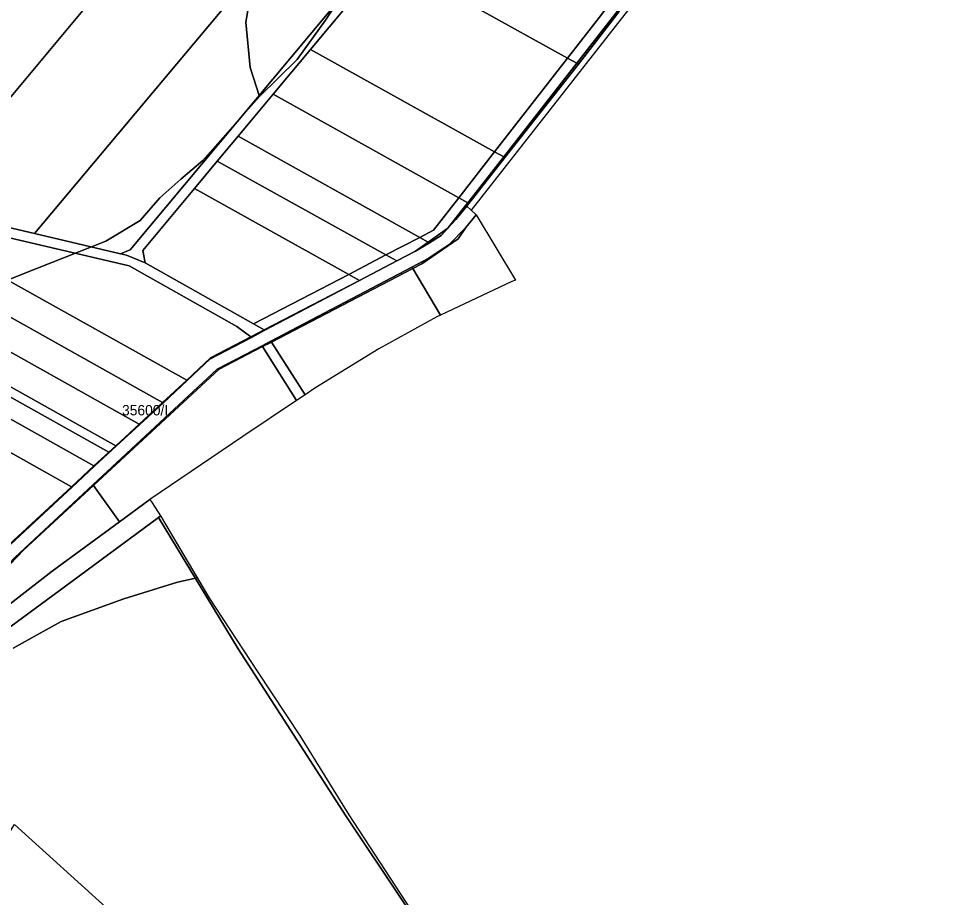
# Model space of a CAD drawing. Extents: x -541351 to -537540, y -1162694 to -1159725.
# Drawn here: x -537985.1 to -537540.1, y -1161335.6 to -1160910.2 of the extents above; entities that cross this region are included whole.
import ezdxf

# ---------------------------------------------------------------- set-up
doc = ezdxf.new("R2010")
doc.units = 0
for name, color, linetype in [('95560013', 7, 'Continuous'), ('95590013', 7, 'Continuous'), ('95610013', 7, 'Continuous'), ('95630013', 7, 'Continuous'), ('95640013', 7, 'Continuous'), ('95660013', 7, 'Continuous')]:
    doc.layers.add(name, color=color, linetype=linetype)

msp = doc.modelspace()

# ---------------------------------------------------------------- linework, layer by layer
at = {"layer": '95560013'}
for points in [[(-538045.37, -1160998.29), (-538077.91, -1160990.66), (-537915.59, -1160797.32), (-537871.51, -1160807.67), (-537952.32, -1160904.42), (-538033.13, -1161001.17)], [(-538033.13, -1161001.17), (-537952.32, -1160904.42), (-537871.51, -1160807.67), (-537815.26, -1160820.89), (-537977.34, -1161014.29)], [(-537815.26, -1160820.89), (-537776.51, -1160829.99), (-537775.04, -1160835.28), (-537853.06, -1160928.71), (-537931.08, -1161022.13), (-537935.72, -1161024.07), (-537977.34, -1161014.29)], [(-537806.91, -1160880.9), (-537790.61, -1160861.47), (-537786.25, -1160856.27), (-537699.93, -1160904.11), (-537704.14, -1160909.52), (-537719.59, -1160929.38)], [(-537806.91, -1160880.9), (-537719.59, -1160929.38), (-537754.86, -1160974.71), (-537843.94, -1160925.28)], [(-537861.98, -1160946.89), (-537843.94, -1160925.28), (-537754.86, -1160974.71), (-537772.19, -1160996.99)], [(-537878.89, -1160967.16), (-537861.98, -1160946.89), (-537772.19, -1160996.99), (-537784.39, -1161012.67), (-537791.07, -1161016.15)], [(-537791.07, -1161016.15), (-537807.37, -1161024.64), (-537888.95, -1160979.22), (-537878.89, -1160967.16)], [(-537825.4, -1161034.03), (-537899.97, -1160992.42), (-537888.95, -1160979.22), (-537807.37, -1161024.64)], [(-537825.4, -1161034.03), (-537871.46, -1161058.02), (-537923.87, -1161028.46), (-537925.02, -1161022.44), (-537899.97, -1160992.42)], [(-537903.69, -1161085.29), (-538044.43, -1161006.74), (-538039.9, -1161004.61), (-537931.57, -1161029.91), (-537879.46, -1161059.19), (-537872.72, -1161064.31), (-537892.24, -1161074.47)], [(-537903.69, -1161085.29), (-537915.45, -1161096.02), (-538051.5, -1161019.74), (-538044.43, -1161006.74)], [(-537941.41, -1161120.13), (-537948.57, -1161126.77), (-538071.97, -1161057.57), (-538067.56, -1161049.39)], [(-538071.97, -1161057.57), (-537948.57, -1161126.77), (-537959.49, -1161136.9), (-538078.6, -1161069.87)], [(-538017.76, -1161193.9), (-538116.49, -1161139.32), (-538078.6, -1161069.87), (-537959.49, -1161136.9), (-537987.47, -1161162.86), (-538017.1, -1161193.19)], [(-537862.95, -1161412.71), (-537904.74, -1161473.13), (-537909.29, -1161473.5), (-537958.26, -1161439.63), (-538014.16, -1161400.98), (-537997.12, -1161376.05), (-538023.45, -1161358.02), (-537986.93, -1161300.34), (-537910.48, -1161369.63)]]:
    msp.add_lwpolyline(points, close=True, dxfattribs=at)
for points in [[(-537806.91, -1160880.9), (-537843.94, -1160925.28), (-537861.98, -1160946.89), (-537878.89, -1160967.16), (-537888.95, -1160979.22), (-537899.97, -1160992.42), (-537925.02, -1161022.44), (-537923.87, -1161028.46), (-537932.92, -1161024.73), (-537935.72, -1161024.07), (-537931.08, -1161022.13), (-537853.06, -1160928.71), (-537775.04, -1160835.28)], [(-537991.61, -1161206.61), (-537962.32, -1161184.95), (-537917.43, -1161151.64), (-537878.78, -1161215.29), (-537826.79, -1161296.05), (-537771.59, -1161378.63), (-537765.56, -1161389.07), (-537763.17, -1161398.15), (-537765.32, -1161412.85), (-537757.44, -1161423.63), (-537734.41, -1161442.14), (-537710.31, -1161497.52), (-537696.57, -1161528.99), (-537674.08, -1161574.59), (-537686.87, -1161591.71), (-537694.5, -1161607.51), (-537696.89, -1161615.11), (-537701.32, -1161616.63), (-537847.19, -1161516.44), (-537903.61, -1161477.42), (-537860.67, -1161414.77), (-537862.95, -1161412.71), (-537910.48, -1161369.63), (-537986.93, -1161300.34)]]:
    msp.add_lwpolyline(points, dxfattribs=at)
at = {"layer": '95590013'}
for points in [[(-537915.45, -1161096.02), (-537926.78, -1161106.53), (-538058.53, -1161032.66), (-538051.5, -1161019.74)], [(-537938.08, -1161117.04), (-538065.5, -1161045.58), (-538058.53, -1161032.66), (-537926.78, -1161106.53)], [(-537938.08, -1161117.04), (-537941.41, -1161120.13), (-538067.56, -1161049.39), (-538065.5, -1161045.58)]]:
    msp.add_lwpolyline(points, close=True, dxfattribs=at)
at = {"layer": '95610013'}
for points in [[(-537768.77, -1161011.34), (-537763.7, -1161005.27), (-537744.73, -1161036.78), (-537746.54, -1161037.51), (-537780.97, -1161053.72), (-537794.44, -1161031.23), (-537790.07, -1161028.95), (-537772.4, -1161016.83)], [(-537862.75, -1161066.81), (-537794.44, -1161031.23), (-537780.97, -1161053.72), (-537782.71, -1161054.54), (-537810.83, -1161070.12), (-537841.77, -1161089.11), (-537846.51, -1161092.3)], [(-537887.98, -1161079.94), (-537867, -1161069.02), (-537850.7, -1161095.11), (-537876.65, -1161112.57), (-537921.55, -1161143.01), (-537936.28, -1161153.8), (-537948.84, -1161136.22)], [(-537996.47, -1161199.19), (-538020.98, -1161219.57), (-538031.39, -1161229.99), (-538034.17, -1161229.06), (-538037.53, -1161225.44), (-538011.8, -1161198.06), (-537982.73, -1161167.56), (-537948.84, -1161136.22), (-537936.28, -1161153.8), (-537968.86, -1161177.68)]]:
    msp.add_lwpolyline(points, close=True, dxfattribs=at)
at = {"layer": '95630013'}
for points in [[(-537552.67, -1160730.05), (-537589.07, -1160776.48), (-537674.22, -1160885.61), (-537766.11, -1161003.04), (-537768.34, -1161000.98), (-537767.32, -1160999.7), (-537749.91, -1160977.46), (-537714.27, -1160932.34), (-537698.94, -1160912.41), (-537694.76, -1160906.98), (-537676.89, -1160884.14), (-537673.82, -1160880.18), (-537628.36, -1160821.2), (-537546.25, -1160717.06), (-537542.86, -1160712.01), (-537540.13, -1160714.12)], [(-537715.05, -1160931.9), (-537699.56, -1160912.07), (-537695.33, -1160906.66), (-537694.76, -1160906.98), (-537698.94, -1160912.41), (-537714.27, -1160932.34)], [(-537714.27, -1160932.34), (-537749.91, -1160977.46), (-537750.43, -1160977.17), (-537715.05, -1160931.9)], [(-537767.32, -1160999.7), (-537767.82, -1160999.43), (-537750.43, -1160977.17), (-537749.91, -1160977.46)], [(-537777.42, -1161011.72), (-537768.74, -1161000.61), (-537768.34, -1161000.98), (-537773.53, -1161007.54)], [(-537768.74, -1161000.61), (-537767.82, -1160999.43), (-537767.32, -1160999.7), (-537768.34, -1161000.98)], [(-537772.4, -1161016.83), (-537790.07, -1161028.95), (-537794.44, -1161031.23), (-537794.88, -1161030.5), (-537786.69, -1161026.16), (-537776.79, -1161019.64), (-537768.77, -1161011.34)], [(-537777.42, -1161011.72), (-537780.69, -1161015.23), (-537786.37, -1161018.78), (-537786.92, -1161018.47)], [(-537793.05, -1161022.83), (-537786.92, -1161018.47), (-537786.37, -1161018.78)], [(-537862.75, -1161066.81), (-537863.04, -1161066.36), (-537794.88, -1161030.5), (-537794.44, -1161031.23)], [(-537820.17, -1161036.95), (-537865.95, -1161061.12), (-537866.26, -1161060.95)], [(-537872.42, -1161064.54), (-537872.72, -1161064.31), (-537866.26, -1161060.95), (-537865.95, -1161061.12)], [(-537872.42, -1161064.54), (-537892.49, -1161075.13), (-537903.54, -1161085.37), (-537903.69, -1161085.29), (-537892.24, -1161074.47), (-537872.72, -1161064.31)], [(-537863.04, -1161066.36), (-537862.75, -1161066.81), (-537867, -1161069.02), (-537867.27, -1161068.59)], [(-537867.27, -1161068.59), (-537867, -1161069.02), (-537887.98, -1161079.94), (-537948.84, -1161136.22), (-537982.73, -1161167.56), (-538011.8, -1161198.06), (-538037.53, -1161225.44), (-538037.84, -1161225.1), (-537986.78, -1161171.01), (-537949.05, -1161135.92), (-537888.93, -1161079.99)], [(-537903.54, -1161085.37), (-537915, -1161096.28), (-537915.45, -1161096.02), (-537903.69, -1161085.29)], [(-537926.78, -1161106.53), (-537915.45, -1161096.02), (-537915, -1161096.28), (-537937.84, -1161117.18), (-537938.08, -1161117.04)], [(-537948.57, -1161126.77), (-537941.41, -1161120.13), (-537938.08, -1161117.04), (-537937.84, -1161117.18), (-537948.3, -1161126.92)], [(-537959.19, -1161137.07), (-537959.49, -1161136.9), (-537948.57, -1161126.77), (-537948.3, -1161126.92)], [(-538017.1, -1161193.19), (-537987.47, -1161162.86), (-537959.49, -1161136.9), (-537959.19, -1161137.07), (-537990.97, -1161166.65), (-538017.4, -1161194.1), (-538017.76, -1161193.9)]]:
    msp.add_lwpolyline(points, close=True, dxfattribs=at)
msp.add_lwpolyline([(-537990.97, -1161166.65), (-537959.19, -1161137.07), (-537948.3, -1161126.92), (-537937.84, -1161117.18), (-537915, -1161096.28), (-537903.54, -1161085.37), (-537892.49, -1161075.13), (-537872.42, -1161064.54), (-537865.95, -1161061.12), (-537820.17, -1161036.95), (-537802.13, -1161027.56), (-537793.05, -1161022.83), (-537786.37, -1161018.78), (-537780.69, -1161015.23), (-537777.42, -1161011.72), (-537773.53, -1161007.54), (-537768.34, -1161000.98), (-537766.11, -1161003.04), (-537763.7, -1161005.27), (-537768.77, -1161011.34), (-537776.79, -1161019.64), (-537786.69, -1161026.16), (-537794.88, -1161030.5), (-537863.04, -1161066.36), (-537867.27, -1161068.59), (-537888.93, -1161079.99), (-537949.05, -1161135.92), (-537986.78, -1161171.01)], dxfattribs=at)
at = {"layer": '95640013'}
for points in [[(-537699.93, -1160904.11), (-537695.33, -1160906.66), (-537699.56, -1160912.07), (-537715.05, -1160931.9), (-537719.59, -1160929.38), (-537704.14, -1160909.52)], [(-537715.05, -1160931.9), (-537750.43, -1160977.17), (-537754.86, -1160974.71), (-537719.59, -1160929.38)], [(-537767.82, -1160999.43), (-537772.19, -1160996.99), (-537754.86, -1160974.71), (-537750.43, -1160977.17)], [(-537777.42, -1161011.72), (-537786.92, -1161018.47), (-537791.07, -1161016.15), (-537784.39, -1161012.67), (-537772.19, -1160996.99), (-537767.82, -1160999.43), (-537768.74, -1161000.61)], [(-537791.07, -1161016.15), (-537786.92, -1161018.47), (-537793.05, -1161022.83), (-537802.13, -1161027.56), (-537807.37, -1161024.64)], [(-537802.13, -1161027.56), (-537820.17, -1161036.95), (-537825.4, -1161034.03), (-537807.37, -1161024.64)], [(-537866.26, -1161060.95), (-537871.46, -1161058.02), (-537825.4, -1161034.03), (-537820.17, -1161036.95)], [(-537862.75, -1161066.81), (-537846.51, -1161092.3), (-537850.7, -1161095.11), (-537867, -1161069.02)]]:
    msp.add_lwpolyline(points, close=True, dxfattribs=at)
for points in [[(-538033.13, -1161001.17), (-537977.34, -1161014.29), (-537935.72, -1161024.07), (-537932.92, -1161024.73), (-537923.87, -1161028.46), (-537871.46, -1161058.02), (-537866.26, -1161060.95), (-537872.72, -1161064.31), (-537879.46, -1161059.19), (-537931.57, -1161029.91), (-538039.9, -1161004.61)], [(-537996.47, -1161199.19), (-537968.86, -1161177.68), (-537936.28, -1161153.8), (-537921.55, -1161143.01), (-537920.43, -1161144.55), (-537916.45, -1161150.91), (-537917.43, -1161151.64), (-537962.32, -1161184.95), (-537991.61, -1161206.61)], [(-537771.59, -1161378.63), (-537826.79, -1161296.05), (-537878.78, -1161215.29), (-537917.43, -1161151.64), (-537916.45, -1161150.91), (-537892.7, -1161190.89), (-537869.6, -1161226.04), (-537848.8, -1161257.55), (-537825.35, -1161295.54), (-537795.27, -1161341.6)]]:
    msp.add_lwpolyline(points, dxfattribs=at)
at = {"layer": '95660013'}
for points in [[(-537990.87, -1161037), (-537975.87, -1161031), (-537942.81, -1161018), (-537926.31, -1161008), (-537916.69, -1160997), (-537906.5, -1160988), (-537895.87, -1160979), (-537876.62, -1160957), (-537868.5, -1160948), (-537850.31, -1160930), (-537836.62, -1160911), (-537817.37, -1160882)], [(-537674.22, -1160885.61), (-537766.11, -1161003.04), (-537763.7, -1161005.27), (-537744.73, -1161036.78), (-537746.54, -1161037.51), (-537780.97, -1161053.72), (-537782.71, -1161054.54), (-537810.83, -1161070.12), (-537841.77, -1161089.11), (-537846.51, -1161092.3), (-537850.7, -1161095.11), (-537876.65, -1161112.57), (-537921.55, -1161143.01), (-537920.43, -1161144.55), (-537916.45, -1161150.91), (-537898.6, -1161180.95), (-537908.12, -1161183), (-537934.19, -1161191), (-537964.37, -1161202), (-537987.62, -1161215)], [(-537817.37, -1160882), (-537836.62, -1160911), (-537850.31, -1160930), (-537868.5, -1160948), (-537873.12, -1160934), (-537875.12, -1160912), (-537871.81, -1160892)], [(-537871.81, -1160892), (-537875.12, -1160912), (-537873.12, -1160934), (-537868.5, -1160948), (-537876.62, -1160957), (-537895.87, -1160979), (-537906.5, -1160988), (-537916.69, -1160997), (-537926.31, -1161008), (-537942.81, -1161018), (-537975.87, -1161031), (-537990.87, -1161037)], [(-537987.62, -1161215), (-537964.37, -1161202), (-537934.19, -1161191), (-537908.12, -1161183), (-537898.6, -1161180.95), (-537892.7, -1161190.89), (-537869.6, -1161226.04), (-537848.8, -1161257.55), (-537825.35, -1161295.54), (-537795.27, -1161341.6)]]:
    msp.add_lwpolyline(points, dxfattribs=at)

# ---------------------------------------------------------------- texts
msp.add_text('35600/I.', height=5, rotation=360, dxfattribs=at).set_placement((-537935, -1161102.28))

doc.saveas('drawing.dxf')
